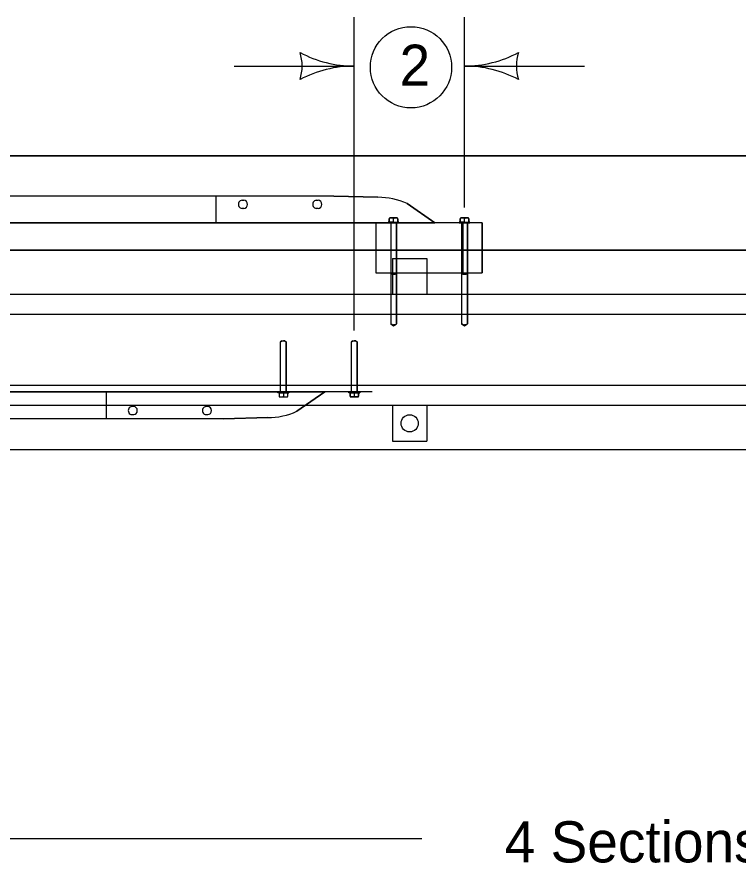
# Model space of a CAD drawing. Extents: x 10028 to 81668, y 3581 to 11018.
# Drawn here: x 17870.2 to 18136.9, y 8565.3 to 8882.3 of the extents above; entities that cross this region are included whole.
import ezdxf

# ---------------------------------------------------------------- set-up
doc = ezdxf.new("R2010")
doc.units = 0
for name, color, linetype in [('conPaving', 7, 'Continuous'), ('dsnCellsNorthArrow', 7, 'Continuous'), ('dsnTextTabulation', 7, 'Continuous'), ('Level 41', 7, 'Continuous'), ('Level 9', 7, 'Continuous')]:
    doc.layers.add(name, color=color, linetype=linetype)

msp = doc.modelspace()

# ---------------------------------------------------------------- linework, layer by layer
at = {"layer": 'conPaving'}
for p, q in [((17987.17, 8816.12), (17702.09, 8816.12)), ((17953.32, 8814.58), (17953.99, 8814.58)), ((17980.74, 8814.58), (17981.41, 8814.58)), ((18003.49, 8815.68), (17987.17, 8816.12)), ((18024.57, 8806.21), (18014.32, 8813.36)), ((17953.99, 8811.61), (17953.32, 8811.61)), ((17981.41, 8811.61), (17980.74, 8811.61)), ((18007.7, 8807.76), (18007.7, 8806.5)), ((18009.57, 8808.08), (18007.98, 8808.08)), ((18010.6, 8808.08), (18009.57, 8808.08)), ((18010.88, 8806.5), (18010.88, 8807.76)), ((18033.91, 8807.76), (18033.91, 8806.5)), ((18033.91, 8807.76), (18033.91, 8806.5)), ((18035.79, 8808.08), (18034.2, 8808.08)), ((18035.79, 8808.08), (18034.2, 8808.08)), ((18036.82, 8808.08), (18035.79, 8808.08)), ((18036.82, 8808.08), (18035.79, 8808.08)), ((18037.1, 8806.5), (18037.1, 8807.76)), ((18037.1, 8806.5), (18037.1, 8807.76)), ((17681.03, 8806.21), (18008.23, 8806.21)), ((18007.7, 8806.5), (18007.3, 8806.5)), ((18007.3, 8806.5), (18007.3, 8806.21)), ((18007.3, 8806.21), (18008.23, 8806.21)), ((18008.23, 8806.21), (18008.23, 8787.72)), ((18008.23, 8806.21), (18008.23, 8768.92)), ((18010.35, 8787.72), (18010.35, 8806.21)), ((18010.35, 8806.21), (18024.57, 8806.21)), ((18010.35, 8768.92), (18010.35, 8806.21)), ((18010.35, 8806.21), (18011.28, 8806.21)), ((18011.28, 8806.5), (18010.88, 8806.5)), ((18011.28, 8806.21), (18011.28, 8806.5)), ((18033.91, 8806.5), (18033.52, 8806.5)), ((18033.52, 8806.5), (18033.52, 8806.21)), ((18033.91, 8806.5), (18033.52, 8806.5)), ((18033.52, 8806.5), (18033.52, 8806.21)), ((18033.52, 8806.21), (18034.44, 8806.21)), ((18033.52, 8806.21), (18034.44, 8806.21)), ((18034.44, 8806.21), (18034.44, 8787.72)), ((18034.44, 8806.21), (18034.44, 8768.92)), ((18036.57, 8787.72), (18036.57, 8806.21)), ((18036.57, 8806.21), (18037.5, 8806.21)), ((18036.57, 8768.92), (18036.57, 8806.21)), ((18036.57, 8806.21), (18037.5, 8806.21)), ((18037.5, 8806.5), (18037.1, 8806.5)), ((18037.5, 8806.5), (18037.1, 8806.5)), ((18037.5, 8806.21), (18037.5, 8806.5)), ((18037.5, 8806.21), (18037.5, 8806.5)), ((18008.23, 8787.72), (18008.76, 8787.34)), ((18008.76, 8787.34), (18009.29, 8787.34)), ((18009.29, 8787.34), (18009.82, 8787.34)), ((18009.82, 8787.34), (18010.35, 8787.72)), ((18034.44, 8787.72), (18034.98, 8787.34)), ((18034.98, 8787.34), (18035.51, 8787.34)), ((18035.51, 8787.34), (18036.04, 8787.34)), ((18036.04, 8787.34), (18036.57, 8787.72)), ((18008.23, 8768.92), (18009.3, 8768.15)), ((18009.3, 8768.16), (18010.35, 8768.92)), ((18009.3, 8768.15), (18009.3, 8768.17)), ((18009.3, 8768.17), (18009.3, 8768.16)), ((18034.44, 8768.92), (18035.51, 8768.15)), ((18035.51, 8768.16), (18036.57, 8768.92)), ((18035.51, 8768.15), (18035.51, 8768.17)), ((18035.51, 8768.17), (18035.51, 8768.16)), ((17967.51, 8762.26), (17968.04, 8762.65)), ((17968.04, 8762.65), (17968.57, 8762.65)), ((17968.57, 8762.65), (17969.1, 8762.65)), ((17969.1, 8762.65), (17969.63, 8762.26)), ((17993.72, 8762.26), (17994.26, 8762.65)), ((17994.26, 8762.65), (17994.79, 8762.65)), ((17994.79, 8762.65), (17995.32, 8762.65)), ((17995.32, 8762.65), (17995.85, 8762.26)), ((17967.51, 8743.77), (17967.51, 8762.26)), ((17969.63, 8762.26), (17969.63, 8743.77)), ((17993.72, 8743.77), (17993.72, 8762.26)), ((17995.85, 8762.26), (17995.85, 8743.77)), ((17640.31, 8743.77), (17967.51, 8743.77)), ((17969.63, 8743.77), (17983.85, 8743.77)), ((17983.85, 8743.77), (17973.6, 8736.63)), ((17992.8, 8743.48), (17992.8, 8743.77)), ((17992.8, 8743.77), (17993.72, 8743.77)), ((17995.85, 8743.77), (17996.78, 8743.77)), ((17996.78, 8743.77), (17996.78, 8743.48)), ((17993.19, 8743.48), (17992.8, 8743.48)), ((17993.19, 8742.22), (17993.19, 8743.48)), ((17995.07, 8741.91), (17993.48, 8741.91)), ((17996.1, 8741.91), (17995.07, 8741.91)), ((17996.78, 8743.48), (17996.38, 8743.48)), ((17996.38, 8743.48), (17996.38, 8742.22)), ((17913.27, 8738.38), (17912.6, 8738.38)), ((17940.69, 8738.38), (17940.02, 8738.38)), ((17912.6, 8735.41), (17913.27, 8735.41)), ((17940.02, 8735.41), (17940.69, 8735.41)), ((17962.77, 8734.3), (17946.45, 8733.87)), ((17946.45, 8733.87), (17661.37, 8733.87))]:
    msp.add_line(p, q, dxfattribs=at)
for centre, major_axis, ratio, start_param, end_param in [((17953.32, 8813.09), (0, 1.49), 0.899999, 0, 3.141593), ((17953.99, 8813.09), (0, 1.49), 0.899999, 3.141593, 6.283185), ((17980.74, 8813.09), (0, 1.49), 0.899999, 0, 3.141593), ((17981.41, 8813.09), (0, 1.49), 0.899999, 3.141593, 6.283185), ((18003.49, 8790.15), (25.97, 0), 0.98332, 1.140354, 1.570796), ((18007.98, 8807.76), (0, 0.315), 0.899999, 0, 1.570796), ((18010.6, 8807.76), (0, 0.315), 0.899999, 4.712389, 6.283185), ((18034.2, 8807.76), (0, -0.315), 0.899999, 3.141593, 4.712389), ((18034.2, 8807.76), (0, 0.315), 0.899999, 0, 1.570796), ((18036.82, 8807.76), (0, -0.315), 0.899999, 1.570796, 3.141593), ((18036.82, 8807.76), (0, 0.315), 0.899999, 4.712389, 6.283185), ((17993.48, 8742.22), (0, -0.315), 0.899999, 4.712389, 6.283185), ((17996.1, 8742.22), (0, -0.315), 0.899999, 6.283185, 7.853982), ((17912.6, 8736.89), (0, 1.49), 0.899999, 0, 3.141593), ((17913.27, 8736.89), (0, 1.49), 0.899999, 3.141593, 6.283185), ((17940.02, 8736.89), (0, 1.49), 0.899999, 0, 3.141593), ((17940.69, 8736.89), (0, 1.49), 0.899999, 3.141593, 6.283185), ((17962.77, 8759.83), (25.97, 0), 0.98332, 4.712389, 5.142831)]:
    msp.add_ellipse(centre, major_axis=major_axis, ratio=ratio, start_param=start_param, end_param=end_param, dxfattribs=at)
at = {"layer": 'dsnTextTabulation'}
for p, q in [((17994.73, 8766.43), (17994.73, 8882.25)), ((18035.45, 8811.92), (18035.45, 8882.25)), ((17950.35, 8864.19), (17994.73, 8864.19)), ((18035.45, 8864.19), (18079.83, 8864.19)), ((18260.99, 8796.14), (17769.47, 8796.14)), ((18260.99, 8779.76), (17769.47, 8779.76)), ((18260.99, 8772.38), (17769.47, 8772.38)), ((18260.99, 8746.17), (17769.47, 8746.17)), ((18260.99, 8738.8), (17769.47, 8738.8)), ((18260.99, 8722.41), (17769.47, 8722.41)), ((17768.44, 8578.73), (18019.77, 8578.73))]:
    msp.add_line(p, q, dxfattribs=at)
msp.add_circle((18015.72, 8863.73), 15, dxfattribs=at)
for centre, radius, start, end in [((17959.09, 8864.19), 16.42, 342.2666, 17.7333), ((17994.73, 8906.69), 42.5, 241.9275, 270), ((17959.09, 8864.19), 16.42, 342.2666, 17.7333), ((17994.73, 8906.69), 42.5, 241.9275, 270), ((18035.45, 8906.69), 42.5, 270, 298.0725), ((18071.08, 8864.19), 16.42, 162.2666, 197.7334), ((17994.73, 8821.69), 42.5, 90, 118.0725), ((17994.73, 8821.69), 42.5, 90, 118.0725), ((18035.45, 8821.69), 42.5, 61.9275, 90)]:
    msp.add_arc(centre, radius, start, end, dxfattribs=at)
at = {"layer": 'Level 41'}
for p, q in [((18008.94, 8793.02), (18021.52, 8793.02)), ((18008.94, 8793.02), (18008.94, 8779.76)), ((18021.52, 8793.02), (18021.52, 8779.76)), ((18008.94, 8738.8), (18008.94, 8725.54)), ((18021.52, 8738.8), (18021.52, 8725.54)), ((18008.94, 8725.54), (18021.52, 8725.54))]:
    msp.add_line(p, q, dxfattribs=at)
msp.add_circle((18015.23, 8732.17), 3.15, dxfattribs=at)
at = {"layer": 'Level 9'}
for p, q in [((17757.59, 8831.02), (19777.13, 8831.02)), ((18257.99, 8831.02), (17848.05, 8831.02)), ((17987.17, 8816.12), (17702.09, 8816.12)), ((17943.76, 8806.21), (17943.76, 8816.12)), ((18007.7, 8806.5), (18007.7, 8807.76)), ((18007.7, 8806.5), (18007.7, 8807.76)), ((18007.98, 8808.08), (18009.01, 8808.08)), ((18007.98, 8808.08), (18009.01, 8808.08)), ((18009.01, 8808.08), (18010.6, 8808.08)), ((18009.01, 8808.08), (18010.6, 8808.08)), ((18009.29, 8806.5), (18009.29, 8807.76)), ((18009.29, 8806.5), (18009.29, 8807.76)), ((18010.88, 8807.76), (18010.88, 8806.5)), ((18010.88, 8807.76), (18010.88, 8806.5)), ((18033.91, 8806.5), (18033.91, 8807.76)), ((18033.91, 8806.5), (18033.91, 8807.76)), ((18034.2, 8808.08), (18035.22, 8808.08)), ((18034.2, 8808.08), (18035.22, 8808.08)), ((18035.22, 8808.08), (18036.82, 8808.08)), ((18035.22, 8808.08), (18036.82, 8808.08)), ((18035.51, 8806.5), (18035.51, 8807.76)), ((18035.51, 8806.5), (18035.51, 8807.76)), ((18037.1, 8807.76), (18037.1, 8806.5)), ((18037.1, 8807.76), (18037.1, 8806.5)), ((18042.06, 8806.21), (17647.2, 8806.21)), ((18002.74, 8806.21), (18002.74, 8787.81)), ((18042.06, 8806.21), (18002.74, 8806.21)), ((18002.74, 8806.21), (18002.74, 8787.81)), ((18009.29, 8806.5), (18007.3, 8806.5)), ((18007.3, 8806.5), (18007.3, 8806.21)), ((18009.29, 8806.5), (18007.3, 8806.5)), ((18007.3, 8806.5), (18007.3, 8806.21)), ((18007.3, 8806.21), (18011.28, 8806.21)), ((18007.3, 8806.21), (18011.28, 8806.21)), ((18007.7, 8806.5), (18010.88, 8806.5)), ((18007.7, 8806.5), (18010.88, 8806.5)), ((18008.23, 8806.21), (18008.23, 8787.72)), ((18008.23, 8806.21), (18008.23, 8768.92)), ((18009.29, 8806.5), (18011.28, 8806.5)), ((18009.29, 8806.5), (18011.28, 8806.5)), ((18009.29, 8806.21), (18010.35, 8806.21)), ((18009.29, 8806.21), (18010.35, 8806.21)), ((18010.35, 8806.21), (18010.35, 8787.72)), ((18010.35, 8806.21), (18010.35, 8768.92)), ((18011.28, 8806.21), (18011.28, 8806.5)), ((18011.28, 8806.21), (18011.28, 8806.5)), ((18035.51, 8806.5), (18033.52, 8806.5)), ((18033.52, 8806.5), (18033.52, 8806.21)), ((18035.51, 8806.5), (18033.52, 8806.5)), ((18033.52, 8806.5), (18033.52, 8806.21)), ((18033.52, 8806.21), (18037.5, 8806.21)), ((18033.52, 8806.21), (18037.5, 8806.21)), ((18033.91, 8806.5), (18037.1, 8806.5)), ((18033.91, 8806.5), (18037.1, 8806.5)), ((18034.44, 8806.21), (18034.44, 8787.72)), ((18034.44, 8806.21), (18034.44, 8768.92)), ((18034.92, 8806.21), (18034.92, 8787.81)), ((18035.51, 8806.5), (18037.5, 8806.5)), ((18035.51, 8806.5), (18037.5, 8806.5)), ((18035.51, 8806.21), (18036.57, 8806.21)), ((18035.51, 8806.21), (18036.57, 8806.21)), ((18036.57, 8806.21), (18036.57, 8787.72)), ((18036.57, 8806.21), (18036.57, 8768.92)), ((18037.5, 8806.21), (18037.5, 8806.5)), ((18037.5, 8806.21), (18037.5, 8806.5)), ((18042.06, 8787.81), (18042.06, 8806.21)), ((18042.06, 8806.21), (18042.06, 8787.81)), ((17848.05, 8796.14), (18260.99, 8796.14)), ((18002.74, 8787.81), (18042.06, 8787.81)), ((18002.74, 8787.81), (18042.06, 8787.81)), ((18008.76, 8787.34), (18008.23, 8787.72)), ((18008.76, 8787.34), (18009.29, 8787.34)), ((18009.82, 8787.34), (18009.29, 8787.34)), ((18009.82, 8787.34), (18010.35, 8787.72)), ((18034.98, 8787.34), (18034.44, 8787.72)), ((18034.98, 8787.34), (18035.51, 8787.34)), ((18036.04, 8787.34), (18035.51, 8787.34)), ((18036.04, 8787.34), (18036.57, 8787.72)), ((18008.76, 8768.54), (18008.23, 8768.92)), ((18008.76, 8768.54), (18009.29, 8768.54)), ((18009.82, 8768.54), (18009.29, 8768.54)), ((18009.82, 8768.54), (18010.35, 8768.92)), ((18034.98, 8768.54), (18034.44, 8768.92)), ((18034.98, 8768.54), (18035.51, 8768.54)), ((18036.04, 8768.54), (18035.51, 8768.54)), ((18036.04, 8768.54), (18036.57, 8768.92)), ((17968.04, 8762.65), (17967.51, 8762.26)), ((17968.04, 8762.65), (17968.57, 8762.65)), ((17969.1, 8762.65), (17968.57, 8762.65)), ((17969.1, 8762.65), (17969.63, 8762.26)), ((17994.26, 8762.65), (17993.72, 8762.26)), ((17994.26, 8762.65), (17994.79, 8762.65)), ((17995.32, 8762.65), (17994.79, 8762.65)), ((17995.32, 8762.65), (17995.85, 8762.26)), ((17967.51, 8743.77), (17967.51, 8762.26)), ((17969.63, 8743.77), (17969.63, 8762.26)), ((17993.72, 8743.77), (17993.72, 8762.26)), ((17995.85, 8743.77), (17995.85, 8762.26)), ((18001.34, 8743.77), (17606.48, 8743.77)), ((17903.04, 8743.77), (17903.04, 8733.87)), ((17966.58, 8743.48), (17966.58, 8743.77)), ((17966.58, 8743.77), (17970.56, 8743.77)), ((17968.57, 8743.77), (17969.63, 8743.77)), ((17970.56, 8743.77), (17970.56, 8743.48)), ((17992.8, 8743.48), (17992.8, 8743.77)), ((17992.8, 8743.77), (17996.78, 8743.77)), ((17994.79, 8743.77), (17995.85, 8743.77)), ((17996.78, 8743.77), (17996.78, 8743.48)), ((17968.57, 8743.48), (17966.58, 8743.48)), ((17966.98, 8743.48), (17970.16, 8743.48)), ((17966.98, 8743.48), (17966.98, 8742.22)), ((17967.26, 8741.91), (17968.29, 8741.91)), ((17968.29, 8741.91), (17969.88, 8741.91)), ((17968.57, 8743.48), (17970.56, 8743.48)), ((17968.57, 8743.48), (17968.57, 8742.22)), ((17970.16, 8742.22), (17970.16, 8743.48)), ((17994.79, 8743.48), (17992.8, 8743.48)), ((17993.19, 8743.48), (17996.38, 8743.48)), ((17993.19, 8743.48), (17993.19, 8742.22)), ((17993.48, 8741.91), (17994.5, 8741.91)), ((17994.5, 8741.91), (17996.1, 8741.91)), ((17994.79, 8743.48), (17996.78, 8743.48)), ((17994.79, 8743.48), (17994.79, 8742.22)), ((17996.38, 8742.22), (17996.38, 8743.48)), ((17946.45, 8733.87), (17661.37, 8733.87))]:
    msp.add_line(p, q, dxfattribs=at)
for points in [[(17953.32, 8814.58), (17953.99, 8814.58)], [(17980.74, 8814.58), (17981.41, 8814.58)], [(17987.17, 8816.12), (18003.49, 8815.68)], [(18014.32, 8813.36), (18024.57, 8806.21)], [(17953.99, 8811.61), (17953.32, 8811.61)], [(17981.41, 8811.61), (17980.74, 8811.61)], [(17973.6, 8736.63), (17983.85, 8743.77)], [(17913.27, 8738.38), (17912.6, 8738.38)], [(17940.69, 8738.38), (17940.02, 8738.38)], [(17912.6, 8735.41), (17913.27, 8735.41)], [(17940.02, 8735.41), (17940.69, 8735.41)], [(17946.45, 8733.87), (17962.77, 8734.3)]]:
    msp.add_lwpolyline(points, dxfattribs=at)
for centre, major_axis, ratio, start_param, end_param in [((17953.32, 8813.09), (0, 1.49), 0.899999, 0, 3.141593), ((17953.99, 8813.09), (0, 1.49), 0.899999, 3.141593, 6.283185), ((17980.74, 8813.09), (0, 1.49), 0.899999, 0, 3.141593), ((17981.41, 8813.09), (0, 1.49), 0.899999, 3.141593, 6.283185), ((18003.49, 8790.15), (25.97, 0), 0.98332, 1.140354, 1.570796), ((18007.98, 8807.76), (0, 0.315), 0.899999, 6.283185, 7.853982), ((18007.98, 8807.76), (0, 0.315), 0.899999, 6.283185, 7.853982), ((18009.01, 8807.76), (0, 0.315), 0.899999, 4.712389, 6.283185), ((18009.01, 8807.76), (0, 0.315), 0.899999, 4.712389, 6.283185), ((18009.57, 8807.76), (0, 0.315), 0.899999, 0, 1.570796), ((18009.57, 8807.76), (0, 0.315), 0.899999, 0, 1.570796), ((18010.6, 8807.76), (0, 0.315), 0.899999, 4.712389, 6.283185), ((18010.6, 8807.76), (0, 0.315), 0.899999, 4.712389, 6.283185), ((18034.2, 8807.76), (0, 0.315), 0.899999, 6.283185, 7.853982), ((18034.2, 8807.76), (0, 0.315), 0.899999, 6.283185, 7.853982), ((18035.22, 8807.76), (0, 0.315), 0.899999, 4.712389, 6.283185), ((18035.22, 8807.76), (0, 0.315), 0.899999, 4.712389, 6.283185), ((18035.79, 8807.76), (0, 0.315), 0.899999, 0, 1.570796), ((18035.79, 8807.76), (0, 0.315), 0.899999, 0, 1.570796), ((18036.82, 8807.76), (0, 0.315), 0.899999, 4.712389, 6.283185), ((18036.82, 8807.76), (0, 0.315), 0.899999, 4.712389, 6.283185), ((17967.26, 8742.22), (0, 0.315), 0.899999, 1.570796, 3.141593), ((17968.29, 8742.22), (0, 0.315), 0.899999, 3.141593, 4.712389), ((17968.85, 8742.22), (0, 0.315), 0.899999, 1.570796, 3.141593), ((17969.88, 8742.22), (0, 0.315), 0.899999, 3.141593, 4.712389), ((17993.48, 8742.22), (0, 0.315), 0.899999, 1.570796, 3.141593), ((17994.5, 8742.22), (0, 0.315), 0.899999, 3.141593, 4.712389), ((17995.07, 8742.22), (0, 0.315), 0.899999, 1.570796, 3.141593), ((17996.1, 8742.22), (0, 0.315), 0.899999, 3.141593, 4.712389), ((17912.6, 8736.89), (0, 1.49), 0.899999, 0, 3.141593), ((17913.27, 8736.89), (0, 1.49), 0.899999, 3.141593, 6.283185), ((17940.02, 8736.89), (0, 1.49), 0.899999, 0, 3.141593), ((17940.69, 8736.89), (0, 1.49), 0.899999, 3.141593, 6.283185), ((17962.77, 8759.83), (25.97, 0), 0.98332, 4.712389, 5.142831)]:
    msp.add_ellipse(centre, major_axis=major_axis, ratio=ratio, start_param=start_param, end_param=end_param, dxfattribs=at)

# ---------------------------------------------------------------- texts
at = {"layer": 'dsnCellsNorthArrow'}
msp.add_text('4 Sections Anchored Temporary Barrier Rail, Concrete', height=15.2, dxfattribs=at).set_placement((18050.36, 8569.93))
at = {"layer": 'dsnTextTabulation'}
msp.add_text('2', height=15.2, dxfattribs=at).set_placement((18011.51, 8856.89))

doc.saveas('drawing.dxf')
